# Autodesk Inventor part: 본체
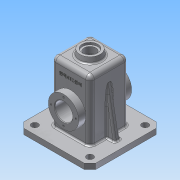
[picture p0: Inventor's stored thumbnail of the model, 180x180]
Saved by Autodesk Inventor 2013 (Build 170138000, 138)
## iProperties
Created: 2016-02
Part Number: 본체
Material: 알루미늄 6061
Document SubType Name: Modeling
Designer: Administrator
Density: 2.71 g/cm^3
Mass: 932.761 g
Surface Area: 1044.48 cm^2
Volume: 344.192 cm^3
Author: Administrator
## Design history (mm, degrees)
sketch "스케치1"
  geometry: L1 (-35, 35)-(35, 35); L2 (35, 35)-(35, -35); L3 (35, -35)-(-35, -35); L4 (-35, -35)-(-35, 35); L5 (-35, 35)-(35, -35); L6 (35, 35)-(-35, -35); 1 further point
  constraints: 12 end point, 2 midpoint, 2 parallel, 1 horizontal, 1 perpendicular
  dimensions: "d0" = 70 distance of L2.end L3.end; "d1" = 70 distance of L1.end L2.end
extrude "돌출1" new body sketch "스케치1" distance "d2" = 110; taper "d3" = 0 deg
feature "쉘1" dims "d4" = 5
fillet "모깎기1" dims "d5" = 8
fillet "모깎기2" dims "d6" = 8
sketch "스케치2"
  geometry: L1 (-30, 30)-(30, 30) reference; L2 (30, 30)-(30, -30) reference; L3 (30, -30)-(-30, -30) reference; L4 (-30, -30)-(-30, 30) reference; L5 (-65, 65)-(65, 65); L6 (65, 65)-(65, -65); L7 (65, -65)-(-65, -65); L8 (-65, -65)-(-65, 65); L9 (-65, 65)-(65, -65); L10 (65, 65)-(-65, -65); 1 further point
  constraints: 12 end point, 2 midpoint, 2 parallel, 1 horizontal, 1 perpendicular
  dimensions: "d7" = 130 distance of L6.end L7.end; "d8" = 130 distance of L5.end L6.end
extrude "돌출2" join sketch "스케치2" distance "d9" = 10; taper "d10" = 0 deg
fillet "모깎기3" dims "d11" = 3
fillet "모깎기4" dims "d12" = 3
sketch "스케치4"
  geometry: L1 (-50, 0)-(-35, 85.069); L2 (35, 102)-(35, 0) reference; L3 (35, 0)-(65, 0) reference; L4 (65, 0)-(65, -10) reference; L5 (65, -10)-(30, -10) reference; L6 (30, -10)-(30, 102) reference; L7 (27, 105)-(-27, 105) reference; L8 (-30, 102)-(-30, -10) reference; L9 (-30, -10)-(-65, -10) reference; L10 (-65, -10)-(-65, 0) reference; L11 (-65, 0)-(-35, 0) reference; L12 (-35, 0)-(-35, 102) reference; L13 (-27, 110)-(27, 110) reference; A1 r 8 centre (27, 102) between (35, 102) and (27, 110) reference; A2 r 3 centre (27, 102) between (30, 102) and (27, 105) reference; A3 r 3 centre (-27, 102) between (-27, 105) and (-30, 102) reference; A4 r 8 centre (-27, 102) between (-27, 110) and (-35, 102) reference; 1 further point
  constraints: 2 end point, 1 midpoint, 1 point on line
  dimensions: "d13" = 10 deg angle of L1 L10; "d14" = 15 distance from line of L1.start L10
feature "리브1" sketch "스케치4" dims "d15" = 10, "d16" = 10, "d17" = 0, "d18" = 0, "d19" = 1, "d20" = 1
sketch "스케치5"
  geometry: L1 (54, 0)-(0, 0) reference; L2 (0, 102)-(0, 0) reference; L3 (0, 102)-(-38, 102) reference; L4 (-38, 102)-(-38, 112) reference; L5 (-38, 112)-(92, 112) reference; L6 (92, 112)-(92, 102) reference; L7 (92, 102)-(54, 102) reference; L8 (54, 102)-(0, 102) reference; L9 (54, 102)-(54, 0) reference; L10 (54, 0)-(0, 0) reference; L11 (0, 102)-(0, 0) reference; L12 (0, 102)-(-38, 102) reference; L13 (-38, 102)-(-38, 112) reference; L14 (-38, 112)-(92, 112) reference; L15 (92, 112)-(92, 102) reference; L16 (92, 102)-(54, 102) reference; L17 (54, 102)-(0, 102) reference; L18 (54, 102)-(54, 0) reference; L19 (92, 102)-(-38, 102) reference; C1 r 27.5 at (27, 57); 2 further points
  constraints: 1 centre point, 1 midpoint, 1 vertical alignment
  dimensions: "d21" = 55 diameter of C1; "d22" = 55 distance from line of L14 C1.centre
extrude "돌출3" join sketch "스케치5" distance "d23" = 13; taper "d24" = 0 deg
sketch "스케치6"
  geometry: L1 (0, 119.416)-(54, 119.416) reference; L2 (61.416, 112)-(61.416, 10) reference; L3 (61.416, 10)-(92, 10) reference; L4 (92, 10)-(92, 0) reference; L5 (92, 0)-(54, 0) reference; L6 (54, 0)-(0, 0) reference; L7 (0, 0)-(-38, 0) reference; L8 (-38, 0)-(-38, 10) reference; L9 (-38, 10)-(-7.416, 10) reference; L10 (-7.416, 10)-(-7.416, 112) reference; L11 (54, 112)-(54, 0) reference; L12 (0, 112)-(54, 112) reference; L13 (0, 0)-(0, 112) reference; L14 (0, 119.416)-(54, 119.416) reference; L15 (61.416, 112)-(61.416, 10) reference; L16 (61.416, 10)-(92, 10) reference; L17 (92, 10)-(92, 0) reference; L18 (92, 0)-(54, 0) reference; L19 (54, 0)-(0, 0) reference; L20 (0, 0)-(-38, 0) reference; L21 (-38, 0)-(-38, 10) reference; L22 (-38, 10)-(-7.416, 10) reference; L23 (-7.416, 10)-(-7.416, 112) reference; L24 (54, 112)-(54, 0) reference; L25 (0, 112)-(54, 112) reference; L26 (0, 0)-(0, 112) reference; C1 r 27.5 at (27, 55) reference; A1 r 7.416 centre (54, 112) between (61.416, 112) and (54, 119.416) reference; A2 r 7.416 centre (0, 112) between (0, 119.416) and (-7.416, 112) reference; A3 r 7.416 centre (54, 112) between (61.416, 112) and (54, 119.416) reference; A4 r 7.416 centre (0, 112) between (0, 119.416) and (-7.416, 112) reference; 1 further point
extrude "돌출4" join sketch "스케치6" distance "d25" = 7; taper "d26" = -45 deg
sketch "스케치8"
  geometry: C1 r 27.5 at (0, 0) reference; C2 r 16 at (0, 0); 1 further point
  constraints: 1 centre point, 1 coincident
  dimensions: "d27" = 32 diameter of C2
extrude "돌출5" cut sketch "스케치8" stored distance "d28" = 7; taper "d29" = 0 deg
chamfer "모따기1" distance "d30" = 1; stored, may be unused: second distance "d31" = 2, angle "d32" = 45 deg
fillet "모깎기5" dims "d33" = 0.5
fillet "모깎기6" dims "d34" = 0.5
sketch "스케치9"
  geometry: C1 r 20 at (0, 0); 1 further point
  constraints: 1 centre point, 1 coincident
  dimensions: "d35" = 40 diameter of C1
extrude "돌출6" join sketch "스케치9" distance "d36" = 10; taper "d37" = -10 deg
hole "구멍1" diameter "d40" = 21; stored, may be unused: countersink angle "d44" = 90 deg, drill point angle "d46" = 0 deg; dims "d38" = 10, "d39" = 10, "d41" = 6, "d42" = 28, "d43" = 4, "d45" = 8
sketch "스케치12"
  geometry: C1 r 27.5 at (0, 0) reference; 2 further points
  constraints: 1 vertical alignment
  dimensions: "d47" = 22.5 distance of C1.centre point (0, -22.5)
hole "구멍2" sketch "스케치12" at (0, -22.5) diameter "d48" = 3.242; stored, may be unused: countersink angle "d52" = 90 deg, drill point angle "d54" = 118 deg; dims "d49" = 8, "d50" = 28, "d51" = 4, "d53" = 10
fillet "모깎기7" dims "d58" = 3
fillet "모깎기8" dims "d59" = 3
fillet "모깎기9" dims "d60" = 3
fillet "모깎기10" dims "d61" = 3
sketch "스케치14"
  geometry: L1 (65, -65)-(65, 65) reference; L2 (65, 65)-(-65, 65) reference; L3 (-65, 65)-(-65, -65) reference; C1 r 6 at (-50, 50); C2 r 6 at (50, 50); 1 further point
  constraints: 2 centre point, 1 horizontal alignment
  dimensions: "d62" = 12 diameter of C1; "d63" = 12 diameter of C2; "d64" = 15 distance from line of L3 C1.centre; "d65" = 15 distance from line of L2 C1.centre; "d66" = 15 distance from line of L1 C2.centre
extrude "돌출7" cut sketch "스케치14" stored distance "d67" = 10; taper "d68" = 0 deg
chamfer "모따기2" distance "d69" = 10; stored, may be unused: second distance "d70" = 2, angle "d71" = 45 deg
sketch "스케치15"
  geometry: L1 (8.763, 18)-(45.237, 18) reference; L2 (62, -99)-(62, 0) reference; 2 further points
  constraints: 1 other
  dimensions: "d72" = 30 distance from line of L1 point (27, -12); "d73" = 35 distance from line of L2 point (27, -12)
feature "엠보싱1" sketch "스케치15" dims "d0" = 70, "d1" = 70, "d74" = 0.5, "d75" = 0
node "솔리드1"
mirror "대칭1"
mirror "대칭2"
pattern_circular "원형 패턴1" dims angle "d56" = 360 deg
mirror "대칭3"
mirror "대칭4"
node "투영된 루프1"
node "절단 모서리 투영1"
node "절단 모서리 투영2"
node "절단 모서리 투영3"
node "절단 모서리 투영4"
node "절단 모서리 투영5"
